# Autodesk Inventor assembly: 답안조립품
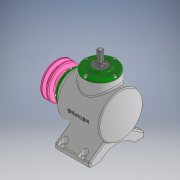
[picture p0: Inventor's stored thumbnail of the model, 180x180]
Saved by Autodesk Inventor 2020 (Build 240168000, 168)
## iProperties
Created: 2023-12
Part Number: 답안조립품
Document SubType Name: Assembly
Designer: 1강의실14
Author: 1강의실14
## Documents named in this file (17)
- C:\Users\1강의실14\Desktop\731203V1006\답안조립품.iam
- C:\Users\1강의실14\Desktop\731203V1006\본체.ipt
- C:\Users\1강의실14\Desktop\731203V1006\커버.ipt
- C:\Users\1강의실14\Desktop\731203V1006\베어링 6203.ipt
- C:\Users\1강의실14\Desktop\731203V1006\오일실 17 x 32 x 8.ipt
- C:\Users\1강의실14\Desktop\731203V1006\서브 축.ipt
- 서브 축.ipt
- C:\Users\1강의실14\Desktop\731203V1006\메인 축.ipt
- 메인 축.ipt
- C:\Users\1강의실14\Desktop\731203V1006\키 5 x 5 x 14.ipt
- C:\Users\1강의실14\Desktop\731203V1006\키 4 x 4 x 14.ipt
- C:\Users\1강의실14\Desktop\731203V1006\메인 베벨기어.ipt
- C:\Users\1강의실14\Desktop\731203V1006\서브 베벨기어.ipt
- C:\Users\1강의실14\Desktop\731203V1006\V-벨트풀리.ipt
- C:\Users\1강의실14\Desktop\731203V1006\육각볼트 M4 x 8.ipt
- C:\Users\1강의실14\Desktop\731203V1006\와셔 4 x 16.ipt
- C:\Users\1강의실14\Desktop\731203V1006\볼트 M4 x 10.ipt
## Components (1 placed, 1 different names)
1. V-벨트풀리:1
